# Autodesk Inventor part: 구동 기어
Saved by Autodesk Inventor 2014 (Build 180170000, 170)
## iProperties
Created: 2026-04
Part Number: 구동 기어
Material: 강철, 합금
Document SubType Name: Modeling
Designer: dg
Density: 7.85 g/cm^3
Appearance: 반연마
Mass: 418.263 g
Surface Area: 157.061 cm^2
Volume: 53.2819 cm^3
Author: jhkim
Creation Date: 2026-03-27
Sending System: Autodesk Inventor 2026
Preprocessor: ST-DEVELOPER v20.1
Author: dg
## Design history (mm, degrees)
node "구동 기어1"
node "솔리드1"
node "기준1"
